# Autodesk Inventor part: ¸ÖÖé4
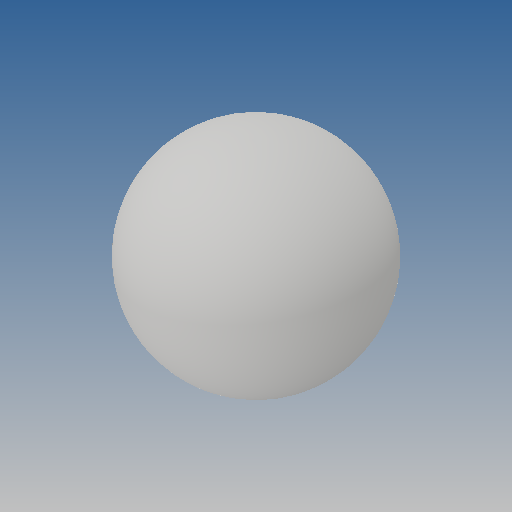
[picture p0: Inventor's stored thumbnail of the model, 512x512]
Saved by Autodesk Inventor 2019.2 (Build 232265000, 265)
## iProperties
Created: 2013-04
Part Number: ¸ÖÖé4
Material: Ogólny
Document SubType Name: Modeling
Designer: CADENGINEERING4
Density: 1 g/cm^3
Appearance: Domyślna
Author: CADENGINEERING4
Revision Number: ÈÎºÎ
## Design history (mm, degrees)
feature "Ðý×ª1"
node "Bryła1"
